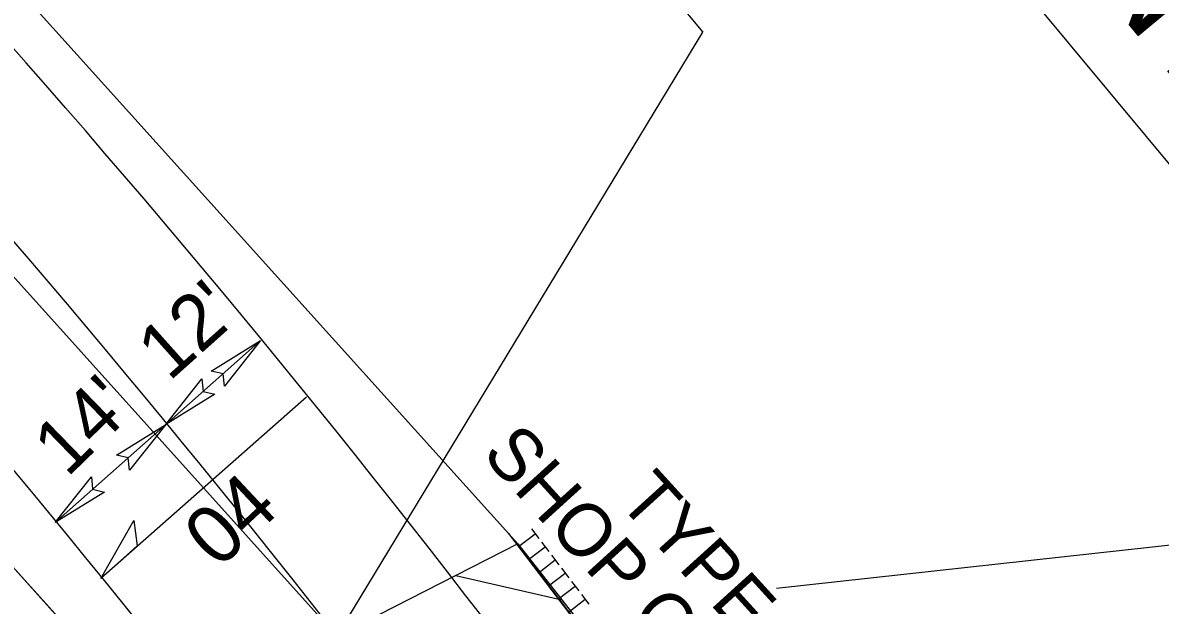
# Model space of a CAD drawing. Extents: x 2057815 to 2059783, y 687683 to 689713.
# Drawn here: x 2058325.2 to 2058433.1, y 688561.8 to 688617 of the extents above; entities that cross this region are included whole.
import ezdxf

# ---------------------------------------------------------------- set-up
doc = ezdxf.new("R2010")
doc.units = 0
for name, color, linetype in [('Prop Approach Slab', 7, 'Continuous'), ('Prop Approach Slab Hatching', 7, 'Continuous'), ('Prop Conc 4in Sidewalk', 7, 'Continuous'), ('Prop DGN Element Guardrail', 7, 'Continuous'), ('Prop Dimension Text', 7, 'Continuous'), ('Prop EOT', 7, 'Continuous'), ('Prop Guardrail Shop Curved', 7, 'Continuous'), ('Prop Horizontal Alignment', 7, 'Continuous'), ('Prop Roadway Bridge', 7, 'Continuous'), ('Prop Structure Anchor Unit CELL', 7, 'Continuous'), ('Prop Superelevation  Arrow CELL', 7, 'Continuous'), ('Prop Superelevation Label', 7, 'Continuous'), ('Prop Terminator CELL', 7, 'Continuous')]:
    doc.layers.add(name, color=color, linetype=linetype)

msp = doc.modelspace()

# ---------------------------------------------------------------- linework, layer by layer
at = {"layer": 'Prop Approach Slab'}
msp.add_line((2058372.16, 688567.61), (2058378.95, 688558.98), dxfattribs=at)
at = {"layer": 'Prop Approach Slab Hatching'}
msp.add_line((2058366.29, 688564.61), (2058376.34, 688562.3), dxfattribs=at)
at = {"layer": 'Prop Conc 4in Sidewalk'}
for p, q in [((2058241.47, 688657.4), (2058337.59, 688550.64)), ((2058337.59, 688550.64), (2058241.47, 688657.4))]:
    msp.add_line(p, q, dxfattribs=at)
at = {"layer": 'Prop DGN Element Guardrail'}
msp.add_arc((2057566.24, 687944.19), 1018.82, 36.7242, 37.79829, dxfattribs=at)
at = {"layer": 'Prop Dimension Text'}
for p, q in [((2058238.89, 688838.76), (2058529.04, 688488.86)), ((2058259.67, 688664.84), (2058355.01, 688558.86)), ((2058386.07, 688620.47), (2058389.68, 688616.12)), ((2058355.01, 688558.86), (2058389.68, 688616.12)), ((2058347.76, 688586.88), (2058338.78, 688578.92)), ((2058338.78, 688578.92), (2058328.3, 688569.63)), ((2058396.68, 688563.42), (2058439.69, 688568.13))]:
    msp.add_line(p, q, dxfattribs=at)
at = {"layer": 'Prop EOT'}
for radius, start, end in [(1012, 31.85515, 52.52584), (986, 31.84967, 52.51508)]:
    msp.add_arc((2057566.24, 687944.19), radius, start, end, dxfattribs=at)
at = {"layer": 'Prop Horizontal Alignment'}
msp.add_arc((2057566.24, 687944.19), 1000, 31.85265, 52.52094, dxfattribs=at)
at = {"layer": 'Prop Roadway Bridge'}
for p, q in [((2058276.73, 688673.54), (2058372.16, 688567.61)), ((2058372.16, 688567.61), (2058332.96, 688547.62))]:
    msp.add_line(p, q, dxfattribs=at)
at = {"layer": 'Prop Structure Anchor Unit CELL'}
for p, q in [((2058371.27, 688568.6), (2058382.63, 688553.68)), ((2058372.22, 688567.35), (2058373.81, 688568.57)), ((2058373.46, 688569.02), (2058374.16, 688568.11)), ((2058373.16, 688566.11), (2058374.76, 688567.32)), ((2058374.41, 688567.78), (2058375.1, 688566.87)), ((2058374.11, 688564.87), (2058375.7, 688566.08)), ((2058375.36, 688566.53), (2058376.05, 688565.62)), ((2058376.3, 688565.29), (2058377, 688564.38)), ((2058375.06, 688563.62), (2058376.65, 688564.84)), ((2058377.25, 688564.05), (2058377.94, 688563.14)), ((2058376, 688562.38), (2058377.6, 688563.59)), ((2058378.2, 688562.81), (2058378.89, 688561.89)), ((2058376.95, 688561.14), (2058378.54, 688562.35))]:
    msp.add_line(p, q, dxfattribs=at)
at = {"layer": 'Prop Superelevation  Arrow CELL'}
msp.add_line((2058352.13, 688581.52), (2058332.62, 688564.33), dxfattribs=at)
msp.add_lwpolyline([(2058332.62, 688564.33), (2058335.76, 688569.81), (2058336.07, 688567.41)], close=True, dxfattribs=at)
at = {"layer": 'Prop Terminator CELL'}
for points in [[(2058343.1, 688583.99), (2058347.76, 688586.88), (2058344.34, 688582.56), (2058344.22, 688583.73)], [(2058343.44, 688581.8), (2058338.78, 688578.92), (2058342.21, 688583.24), (2058342.33, 688582.06)], [(2058334.12, 688576.03), (2058338.78, 688578.92), (2058335.35, 688574.6), (2058335.23, 688575.77)], [(2058332.96, 688572.52), (2058328.3, 688569.63), (2058331.73, 688573.95), (2058331.85, 688572.78)]]:
    msp.add_lwpolyline(points, close=True, dxfattribs=at)

# ---------------------------------------------------------------- texts
at = {"layer": 'Prop Dimension Text'}
for s, height, rotation, p in [('SKETCH SHOWING BRIDGE/PAVEMENT RELATIONSHIP', 9.45, 309.6672, (2058282.36, 688794.91)), ("12'", 5.25, 41.7619, (2058339.1, 688582.94)), ("14'", 5.25, 44.1842, (2058329.43, 688573.83)), ('NOTE: THE BRIDGE IS DESIGNED ON THE ', 7, 309.6672, (2058240.82, 688560.96))]:
    msp.add_text(s, height=height, rotation=rotation, dxfattribs=at).set_placement(p)
at = {"layer": 'Prop Guardrail Shop Curved'}
for s, p in [('SHOP CURVED', (2058368.64, 688576.04)), ('TYPE-III', (2058381.52, 688571.61))]:
    msp.add_text(s, height=5, rotation=312.2591, dxfattribs=at).set_placement(p)
at = {"layer": 'Prop Superelevation Label'}
msp.add_text('04', height=5.5, rotation=43.1135, dxfattribs=at).set_placement((2058343.77, 688565.12))

doc.saveas('drawing.dxf')
